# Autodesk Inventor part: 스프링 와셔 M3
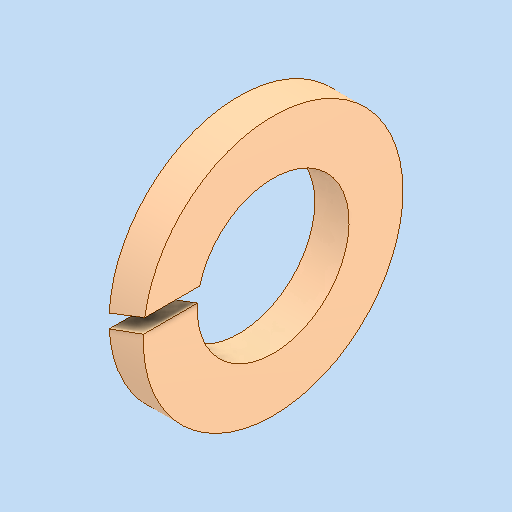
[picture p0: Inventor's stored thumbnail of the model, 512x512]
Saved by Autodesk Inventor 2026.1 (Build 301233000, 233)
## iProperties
Created: 2025-09
Part Number: 스프링 와셔 M3
Material: 강철, 연강
Description: 스프링 잠금 와셔
Document SubType Name: Modeling
Designer: PC-30
Density: 7.85 g/cm^3
Appearance: 기본값
Author: jhkim
Sending System: Autodesk Inventor 2026
Preprocessor: ST-DEVELOPER v20.1
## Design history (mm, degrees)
feature "Solid1"
node "솔리드1"
